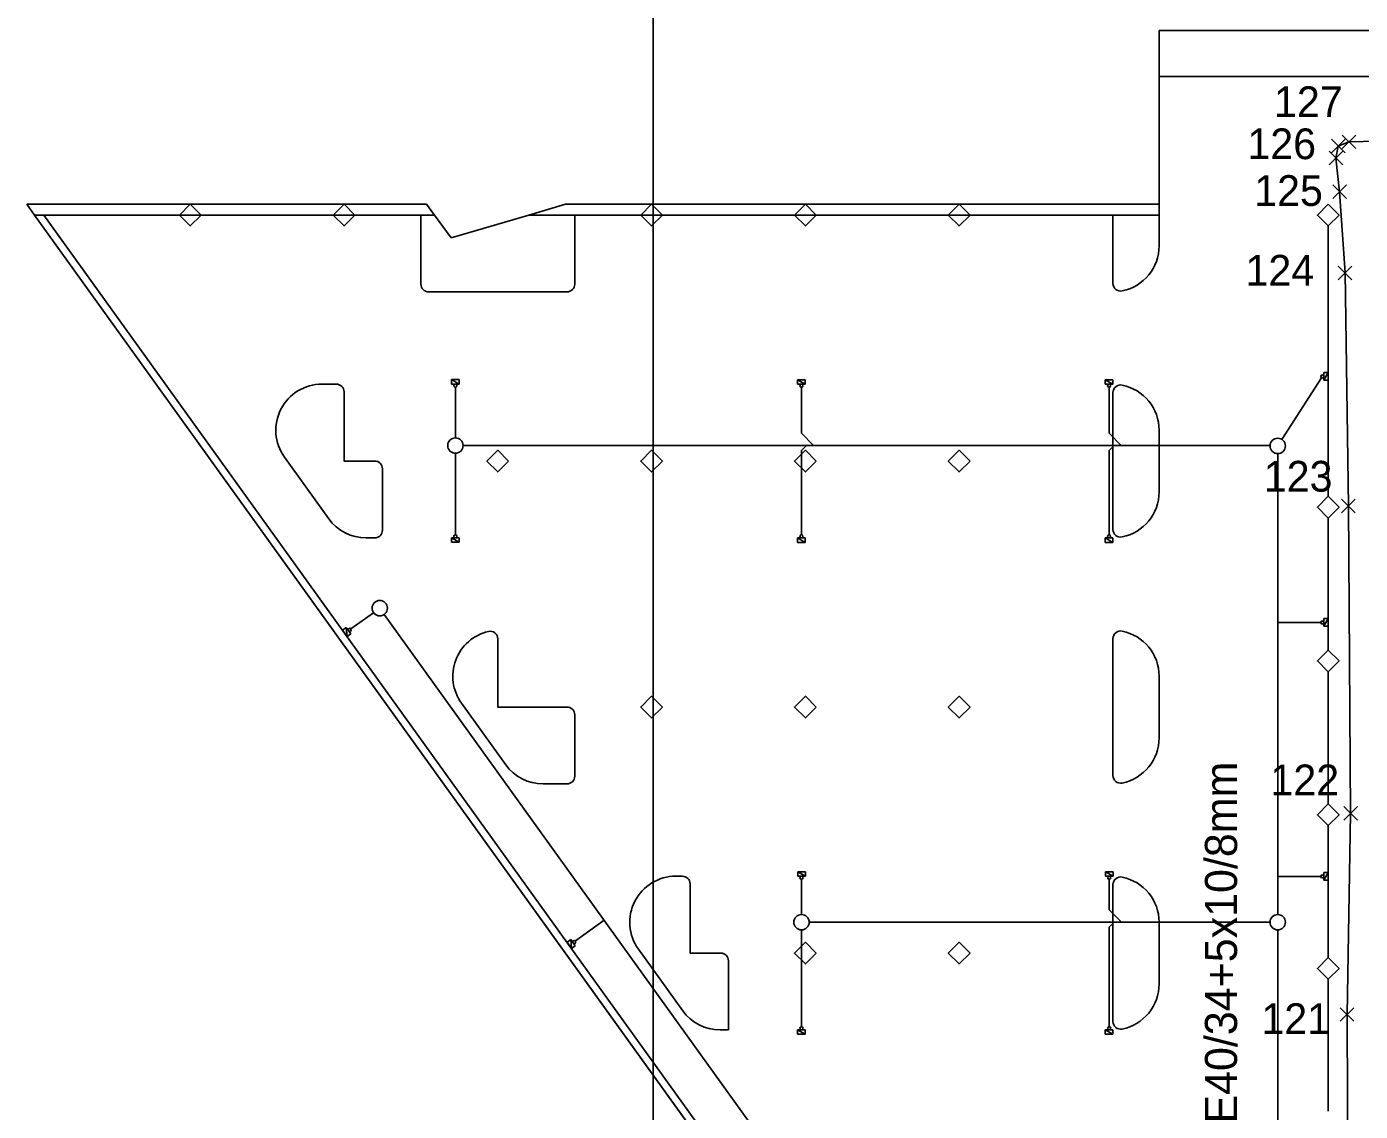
# Model space of a CAD drawing. Extents: x -264205 to -263744, y -1242450 to -1242050.
# Drawn here: x -264205.2 to -264118.5, y -1242249.8 to -1242179.2 of the extents above; entities that cross this region are included whole.
import ezdxf

# ---------------------------------------------------------------- set-up
doc = ezdxf.new("R2010")
doc.units = 0
for name, color, linetype in [('KFA_63-1_TELEKOM_PRELOZKA', 7, 'Continuous'), ('KFA_BODY_CISLO', 7, 'Continuous'), ('KFA_BODY_SYMBOL', 7, 'Continuous'), ('KFA_SITUACIA_DSP', 7, 'Continuous'), ('POPIS', 7, 'Continuous'), ('RAM_NA_TLAC_A3_1-1000', 7, 'Continuous')]:
    doc.layers.add(name, color=color, linetype=linetype)

msp = doc.modelspace()

# ---------------------------------------------------------------- linework, layer by layer
at = {"layer": 'KFA_63-1_TELEKOM_PRELOZKA'}
msp.add_lwpolyline([(-264117.865, -1242295.81), (-264119.153, -1242294.416), (-264119.323, -1242292.348), (-264119.1, -1242276.55), (-264119.268, -1242260.421), (-264119.343, -1242243.475), (-264119.114, -1242230.399), (-264119.258, -1242210.402), (-264119.476, -1242195.245), (-264119.832, -1242189.966), (-264120.07, -1242187.778), (-264119.914, -1242186.996), (-264119.225, -1242186.724), (-264097.679, -1242186.215)], dxfattribs=at)
at = {"layer": 'KFA_BODY_SYMBOL'}
for p, q in [((-264119.667, -1242187.166), (-264118.783, -1242186.282)), ((-264118.783, -1242187.166), (-264119.667, -1242186.282)), ((-264120.356, -1242187.438), (-264119.472, -1242186.554)), ((-264119.472, -1242187.438), (-264120.356, -1242186.554)), ((-264119.914, -1242186.996), (-264119.914, -1242186.996)), ((-264119.225, -1242186.724), (-264119.225, -1242186.724)), ((-264120.512, -1242188.22), (-264119.628, -1242187.336)), ((-264119.628, -1242188.22), (-264120.512, -1242187.336)), ((-264120.07, -1242187.778), (-264120.07, -1242187.778)), ((-264120.274, -1242190.408), (-264119.39, -1242189.524)), ((-264119.39, -1242190.408), (-264120.274, -1242189.524)), ((-264119.832, -1242189.966), (-264119.832, -1242189.966)), ((-264119.918, -1242195.687), (-264119.034, -1242194.803)), ((-264119.034, -1242195.687), (-264119.918, -1242194.803)), ((-264119.476, -1242195.245), (-264119.476, -1242195.245)), ((-264119.7, -1242210.844), (-264118.816, -1242209.96)), ((-264118.816, -1242210.844), (-264119.7, -1242209.96)), ((-264119.258, -1242210.402), (-264119.258, -1242210.402)), ((-264119.556, -1242230.841), (-264118.672, -1242229.957)), ((-264118.672, -1242230.841), (-264119.556, -1242229.957)), ((-264119.114, -1242230.399), (-264119.114, -1242230.399)), ((-264119.785, -1242243.917), (-264118.901, -1242243.033)), ((-264118.901, -1242243.917), (-264119.785, -1242243.033)), ((-264119.343, -1242243.475), (-264119.343, -1242243.475))]:
    msp.add_line(p, q, dxfattribs=at)
at = {"layer": 'KFA_SITUACIA_DSP'}
for p, q in [((-264131.568, -1242193.482), (-264131.568, -1242179.482)), ((-264077.23, -1242179.482), (-264131.568, -1242179.482)), ((-264131.568, -1242179.482), (-264131.568, -1242191.482)), ((-264131.568, -1242179.482), (-263959.468, -1242179.482)), ((-263959.468, -1242179.482), (-264131.568, -1242179.482)), ((-264045.204, -1242182.482), (-264131.568, -1242182.482)), ((-264205.202, -1242190.775), (-264179.193, -1242190.775)), ((-264205.202, -1242190.775), (-264204.694, -1242191.482)), ((-264178.679, -1242191.482), (-264204.694, -1242191.482)), ((-264204.694, -1242191.482), (-264115.871, -1242314.982)), ((-264179.568, -1242191.482), (-264204.078, -1242191.482)), ((-264204.078, -1242191.482), (-264119.75, -1242308.732)), ((-264179.568, -1242191.482), (-264179.568, -1242195.982)), ((-264179.193, -1242190.775), (-264178.679, -1242191.482)), ((-264177.6, -1242192.97), (-264178.679, -1242191.482)), ((-264172.558, -1242191.482), (-264177.6, -1242192.97)), ((-264172.558, -1242191.482), (-264170.162, -1242190.775)), ((-264131.568, -1242191.482), (-264172.558, -1242191.482)), ((-264170.162, -1242190.775), (-264131.568, -1242190.775)), ((-264134.568, -1242191.482), (-264169.568, -1242191.482)), ((-264169.568, -1242195.982), (-264169.568, -1242191.482)), ((-264134.568, -1242195.932), (-264134.568, -1242191.482)), ((-264120.568, -1242192.189), (-264120.568, -1242209.775)), ((-264179.068, -1242196.482), (-264170.068, -1242196.482)), ((-264120.858, -1242202.232), (-264120.858, -1242201.732)), ((-264120.858, -1242201.732), (-264120.568, -1242201.732)), ((-264120.858, -1242202.232), (-264120.568, -1242201.732)), ((-264120.858, -1242202.232), (-264120.568, -1242201.732)), ((-264120.568, -1242201.732), (-264120.858, -1242201.732)), ((-264120.858, -1242201.732), (-264120.858, -1242202.232)), ((-264120.568, -1242201.732), (-264120.568, -1242202.232)), ((-264185.068, -1242202.482), (-264186.002, -1242202.482)), ((-264177.574, -1242202.186), (-264177.074, -1242202.186)), ((-264177.574, -1242202.476), (-264177.574, -1242202.186)), ((-264177.574, -1242202.186), (-264177.074, -1242202.476)), ((-264177.574, -1242202.186), (-264177.074, -1242202.476)), ((-264177.074, -1242202.186), (-264177.574, -1242202.186)), ((-264177.074, -1242202.476), (-264177.574, -1242202.476)), ((-264177.324, -1242202.676), (-264177.324, -1242205.976)), ((-264177.074, -1242202.186), (-264177.074, -1242202.476)), ((-264177.074, -1242202.476), (-264177.074, -1242202.186)), ((-264155.074, -1242202.192), (-264154.574, -1242202.192)), ((-264155.074, -1242202.482), (-264155.074, -1242202.192)), ((-264155.074, -1242202.192), (-264154.574, -1242202.482)), ((-264155.074, -1242202.192), (-264154.574, -1242202.482)), ((-264154.574, -1242202.192), (-264155.074, -1242202.192)), ((-264154.574, -1242202.482), (-264155.074, -1242202.482)), ((-264154.824, -1242202.682), (-264154.824, -1242205.68)), ((-264154.574, -1242202.192), (-264154.574, -1242202.482)), ((-264154.574, -1242202.482), (-264154.574, -1242202.192)), ((-264135.068, -1242202.192), (-264134.568, -1242202.192)), ((-264135.068, -1242202.482), (-264135.068, -1242202.192)), ((-264135.068, -1242202.192), (-264134.568, -1242202.482)), ((-264135.068, -1242202.192), (-264134.568, -1242202.482)), ((-264134.568, -1242202.192), (-264135.068, -1242202.192)), ((-264134.568, -1242202.482), (-264135.068, -1242202.482)), ((-264134.818, -1242202.682), (-264134.818, -1242205.68)), ((-264134.568, -1242202.192), (-264134.568, -1242202.482)), ((-264134.568, -1242202.482), (-264134.568, -1242202.192)), ((-264121.012, -1242202.066), (-264123.585, -1242206.079)), ((-264120.568, -1242202.232), (-264120.858, -1242202.232)), ((-264134.568, -1242203.033), (-264134.568, -1242211.932)), ((-264154.824, -1242205.68), (-264154.029, -1242206.476)), ((-264134.818, -1242205.68), (-264134.023, -1242206.476)), ((-264131.568, -1242209.482), (-264131.568, -1242205.482)), ((-264177.324, -1242212.276), (-264177.324, -1242206.976)), ((-264176.824, -1242206.476), (-264124.354, -1242206.476)), ((-264154.824, -1242206.801), (-264154.499, -1242206.476)), ((-264154.824, -1242212.282), (-264154.824, -1242206.801)), ((-264134.818, -1242206.801), (-264134.493, -1242206.476)), ((-264134.818, -1242212.282), (-264134.818, -1242206.801)), ((-264123.854, -1242207), (-264123.854, -1242236.976)), ((-264188.438, -1242207.234), (-264185.561, -1242211.234)), ((-264182.068, -1242211.982), (-264182.068, -1242207.982)), ((-264120.568, -1242211.189), (-264120.568, -1242219.774)), ((-264183.125, -1242212.482), (-264182.568, -1242212.482)), ((-264177.574, -1242212.476), (-264177.074, -1242212.476)), ((-264177.574, -1242212.766), (-264177.574, -1242212.476)), ((-264177.574, -1242212.476), (-264177.074, -1242212.766)), ((-264177.574, -1242212.476), (-264177.074, -1242212.766)), ((-264177.074, -1242212.476), (-264177.574, -1242212.476)), ((-264177.074, -1242212.766), (-264177.574, -1242212.766)), ((-264177.074, -1242212.476), (-264177.074, -1242212.766)), ((-264177.074, -1242212.766), (-264177.074, -1242212.476)), ((-264155.074, -1242212.482), (-264154.574, -1242212.482)), ((-264155.074, -1242212.772), (-264155.074, -1242212.482)), ((-264155.074, -1242212.482), (-264154.574, -1242212.772)), ((-264155.074, -1242212.482), (-264154.574, -1242212.772)), ((-264154.574, -1242212.482), (-264155.074, -1242212.482)), ((-264154.574, -1242212.772), (-264155.074, -1242212.772)), ((-264154.574, -1242212.482), (-264154.574, -1242212.772)), ((-264154.574, -1242212.772), (-264154.574, -1242212.482)), ((-264135.068, -1242212.482), (-264134.568, -1242212.482)), ((-264135.068, -1242212.772), (-264135.068, -1242212.482)), ((-264135.068, -1242212.482), (-264134.568, -1242212.772)), ((-264135.068, -1242212.482), (-264134.568, -1242212.772)), ((-264134.568, -1242212.482), (-264135.068, -1242212.482)), ((-264134.568, -1242212.772), (-264135.068, -1242212.772)), ((-264134.568, -1242212.482), (-264134.568, -1242212.772)), ((-264134.568, -1242212.772), (-264134.568, -1242212.482)), ((-264184.115, -1242218.399), (-264182.649, -1242217.344)), ((-264181.951, -1242217.458), (-264153.34, -1242257.238)), ((-264184.659, -1242218.482), (-264184.424, -1242218.313)), ((-264184.367, -1242218.888), (-264184.659, -1242218.482)), ((-264184.424, -1242218.313), (-264184.132, -1242218.719)), ((-264184.424, -1242218.313), (-264184.367, -1242218.888)), ((-264184.424, -1242218.313), (-264184.367, -1242218.888)), ((-264184.132, -1242218.719), (-264184.424, -1242218.313)), ((-264121.058, -1242217.982), (-264123.854, -1242217.982)), ((-264120.86, -1242218.232), (-264120.86, -1242217.732)), ((-264120.86, -1242217.732), (-264120.57, -1242217.732)), ((-264120.86, -1242218.232), (-264120.57, -1242217.732)), ((-264120.86, -1242218.232), (-264120.57, -1242217.732)), ((-264120.57, -1242217.732), (-264120.86, -1242217.732)), ((-264120.86, -1242217.732), (-264120.86, -1242218.232)), ((-264120.57, -1242218.232), (-264120.86, -1242218.232)), ((-264120.57, -1242217.732), (-264120.57, -1242218.232)), ((-264184.132, -1242218.719), (-264184.367, -1242218.888)), ((-264184.367, -1242218.888), (-264184.132, -1242218.719)), ((-264134.568, -1242219.033), (-264134.568, -1242227.932)), ((-264131.568, -1242225.482), (-264131.568, -1242221.482)), ((-264120.568, -1242221.189), (-264120.568, -1242229.774)), ((-264176.93, -1242223.234), (-264174.054, -1242227.234)), ((-264169.568, -1242227.982), (-264169.568, -1242223.982)), ((-264171.618, -1242228.482), (-264170.068, -1242228.482)), ((-264120.568, -1242231.189), (-264120.568, -1242239.774)), ((-264162.988, -1242234.482), (-264162.568, -1242234.482)), ((-264155.068, -1242234.192), (-264154.568, -1242234.192)), ((-264155.068, -1242234.482), (-264155.068, -1242234.192)), ((-264155.068, -1242234.192), (-264154.568, -1242234.482)), ((-264155.068, -1242234.192), (-264154.568, -1242234.482)), ((-264154.568, -1242234.192), (-264155.068, -1242234.192)), ((-264154.568, -1242234.482), (-264155.068, -1242234.482)), ((-264154.818, -1242234.682), (-264154.818, -1242236.976)), ((-264154.568, -1242234.192), (-264154.568, -1242234.482)), ((-264154.568, -1242234.482), (-264154.568, -1242234.192)), ((-264135.061, -1242234.192), (-264134.561, -1242234.192)), ((-264135.061, -1242234.482), (-264135.061, -1242234.192)), ((-264135.061, -1242234.192), (-264134.561, -1242234.482)), ((-264135.061, -1242234.192), (-264134.561, -1242234.482)), ((-264134.561, -1242234.192), (-264135.061, -1242234.192)), ((-264134.561, -1242234.482), (-264135.061, -1242234.482)), ((-264134.811, -1242234.682), (-264134.811, -1242236.68)), ((-264134.561, -1242234.192), (-264134.561, -1242234.482)), ((-264134.561, -1242234.482), (-264134.561, -1242234.192)), ((-264121.058, -1242234.499), (-264123.854, -1242234.499)), ((-264120.858, -1242234.749), (-264120.858, -1242234.249)), ((-264120.858, -1242234.249), (-264120.568, -1242234.249)), ((-264120.858, -1242234.749), (-264120.568, -1242234.249)), ((-264120.858, -1242234.749), (-264120.568, -1242234.249)), ((-264120.568, -1242234.249), (-264120.858, -1242234.249)), ((-264120.858, -1242234.249), (-264120.858, -1242234.749)), ((-264120.568, -1242234.749), (-264120.858, -1242234.749)), ((-264120.568, -1242234.249), (-264120.568, -1242234.749)), ((-264162.068, -1242239.482), (-264162.068, -1242234.982)), ((-264134.568, -1242235.033), (-264134.568, -1242243.932)), ((-264134.811, -1242236.68), (-264134.016, -1242237.476)), ((-264169.518, -1242238.695), (-264167.646, -1242237.348)), ((-264154.318, -1242237.476), (-264124.354, -1242237.476)), ((-264134.811, -1242237.801), (-264134.486, -1242237.476)), ((-264131.568, -1242241.482), (-264131.568, -1242237.482)), ((-264154.824, -1242244.276), (-264154.824, -1242237.976)), ((-264134.811, -1242244.276), (-264134.811, -1242237.801)), ((-264123.854, -1242237.976), (-264123.854, -1242297.736)), ((-264170.062, -1242238.778), (-264169.827, -1242238.609)), ((-264169.77, -1242239.184), (-264170.062, -1242238.778)), ((-264169.827, -1242238.609), (-264169.535, -1242239.015)), ((-264169.827, -1242238.609), (-264169.77, -1242239.184)), ((-264169.827, -1242238.609), (-264169.77, -1242239.184)), ((-264169.535, -1242239.015), (-264169.827, -1242238.609)), ((-264169.535, -1242239.015), (-264169.77, -1242239.184)), ((-264169.77, -1242239.184), (-264169.535, -1242239.015)), ((-264165.423, -1242239.234), (-264162.546, -1242243.234)), ((-264162.068, -1242239.482), (-264160.068, -1242239.482)), ((-264159.568, -1242239.982), (-264159.568, -1242244.482)), ((-264120.568, -1242241.189), (-264120.568, -1242249.774)), ((-264160.111, -1242244.482), (-264159.568, -1242244.482)), ((-264155.074, -1242244.476), (-264154.574, -1242244.476)), ((-264155.074, -1242244.766), (-264155.074, -1242244.476)), ((-264155.074, -1242244.476), (-264154.574, -1242244.766)), ((-264155.074, -1242244.476), (-264154.574, -1242244.766)), ((-264154.574, -1242244.476), (-264155.074, -1242244.476)), ((-264154.574, -1242244.476), (-264154.574, -1242244.766)), ((-264154.574, -1242244.766), (-264154.574, -1242244.476)), ((-264135.068, -1242244.476), (-264134.568, -1242244.476)), ((-264135.068, -1242244.766), (-264135.068, -1242244.476)), ((-264135.068, -1242244.476), (-264134.568, -1242244.766)), ((-264135.068, -1242244.476), (-264134.568, -1242244.766)), ((-264134.568, -1242244.476), (-264135.068, -1242244.476)), ((-264134.568, -1242244.476), (-264134.568, -1242244.766)), ((-264134.568, -1242244.766), (-264134.568, -1242244.476)), ((-264154.574, -1242244.766), (-264155.074, -1242244.766)), ((-264134.568, -1242244.766), (-264135.068, -1242244.766))]:
    msp.add_line(p, q, dxfattribs=at)
for points in [[(-264204.694, -1242191.482), (-264137.78, -1242284.52), (-264125.581, -1242301.482)], [(-264193.861, -1242191.482), (-264193.861, -1242191.482), (-264194.568, -1242192.189), (-264195.275, -1242191.482)], [(-264183.861, -1242191.482), (-264183.861, -1242191.482), (-264184.568, -1242192.189), (-264185.275, -1242191.482)], [(-264163.861, -1242191.482), (-264163.861, -1242191.482), (-264164.568, -1242192.189), (-264165.275, -1242191.482)], [(-264153.861, -1242191.482), (-264153.861, -1242191.482), (-264154.568, -1242192.189), (-264155.275, -1242191.482)], [(-264143.861, -1242191.482), (-264143.861, -1242191.482), (-264144.568, -1242192.189), (-264145.275, -1242191.482)], [(-264182.568, -1242207.482), (-264184.568, -1242207.482), (-264184.568, -1242202.982)], [(-264170.068, -1242223.482), (-264174.568, -1242223.482), (-264174.568, -1242219.049)]]:
    msp.add_lwpolyline(points, dxfattribs=at)
for points in [[(-264194.568, -1242190.775), (-264193.861, -1242191.482), (-264194.568, -1242192.189), (-264195.275, -1242191.482)], [(-264184.568, -1242190.775), (-264183.861, -1242191.482), (-264184.568, -1242192.189), (-264185.275, -1242191.482)], [(-264164.568, -1242190.775), (-264163.861, -1242191.482), (-264164.568, -1242192.189), (-264165.275, -1242191.482)], [(-264154.568, -1242190.775), (-264153.861, -1242191.482), (-264154.568, -1242192.189), (-264155.275, -1242191.482)], [(-264144.568, -1242190.775), (-264143.861, -1242191.482), (-264144.568, -1242192.189), (-264145.275, -1242191.482)], [(-264120.568, -1242190.775), (-264119.861, -1242191.482), (-264120.568, -1242192.189), (-264121.275, -1242191.482)], [(-264173.861, -1242207.482), (-264174.568, -1242206.775), (-264175.275, -1242207.482), (-264174.568, -1242208.189)], [(-264163.861, -1242207.482), (-264164.568, -1242206.775), (-264165.275, -1242207.482), (-264164.568, -1242208.189)], [(-264153.861, -1242207.482), (-264154.568, -1242206.775), (-264155.275, -1242207.482), (-264154.568, -1242208.189)], [(-264143.861, -1242207.482), (-264144.568, -1242206.775), (-264145.275, -1242207.482), (-264144.568, -1242208.189)], [(-264120.568, -1242209.775), (-264119.861, -1242210.482), (-264120.568, -1242211.189), (-264121.275, -1242210.482)], [(-264120.568, -1242219.775), (-264119.861, -1242220.482), (-264120.568, -1242221.189), (-264121.275, -1242220.482)], [(-264163.861, -1242223.482), (-264164.568, -1242222.775), (-264165.275, -1242223.482), (-264164.568, -1242224.189)], [(-264153.861, -1242223.482), (-264154.568, -1242222.775), (-264155.275, -1242223.482), (-264154.568, -1242224.189)], [(-264143.861, -1242223.482), (-264144.568, -1242222.775), (-264145.275, -1242223.482), (-264144.568, -1242224.189)], [(-264120.568, -1242229.775), (-264119.861, -1242230.482), (-264120.568, -1242231.189), (-264121.275, -1242230.482)], [(-264153.861, -1242239.482), (-264154.568, -1242238.775), (-264155.275, -1242239.482), (-264154.568, -1242240.189)], [(-264143.861, -1242239.482), (-264144.568, -1242238.775), (-264145.275, -1242239.482), (-264144.568, -1242240.189)], [(-264120.568, -1242239.775), (-264119.861, -1242240.482), (-264120.568, -1242241.189), (-264121.275, -1242240.482)]]:
    msp.add_lwpolyline(points, close=True, dxfattribs=at)
for centre, radius in [((-264120.958, -1242201.982), 0.1), ((-264177.324, -1242202.576), 0.1), ((-264154.824, -1242202.582), 0.1), ((-264134.818, -1242202.582), 0.1), ((-264177.324, -1242206.476), 0.5), ((-264123.854, -1242206.5), 0.5), ((-264177.324, -1242212.376), 0.1), ((-264154.824, -1242212.382), 0.1), ((-264134.818, -1242212.382), 0.1), ((-264182.243, -1242217.052), 0.5), ((-264184.194, -1242218.461), 0.1), ((-264120.958, -1242217.982), 0.1), ((-264154.818, -1242234.582), 0.1), ((-264134.811, -1242234.582), 0.1), ((-264120.958, -1242234.499), 0.1), ((-264154.818, -1242237.476), 0.5), ((-264123.854, -1242237.476), 0.5), ((-264169.597, -1242238.757), 0.1), ((-264154.818, -1242244.376), 0.1), ((-264134.811, -1242244.376), 0.1)]:
    msp.add_circle(centre, radius, dxfattribs=at)
for centre, radius, start, end in [((-264134.568, -1242193.482), 3, 281.53696, 0), ((-264134.068, -1242195.932), 0.5, 180, 281.53696), ((-264179.068, -1242195.982), 0.5, 180, 270), ((-264170.068, -1242195.982), 0.5, 270, 0), ((-264186.002, -1242205.482), 3, 90, 215.72401), ((-264185.068, -1242202.982), 0.5, 0, 90), ((-264134.068, -1242203.033), 0.5, 78.46304, 180), ((-264134.568, -1242205.482), 3, 0, 78.46304), ((-264182.568, -1242207.982), 0.5, 0, 90), ((-264134.568, -1242209.482), 3, 281.53696, 0), ((-264183.125, -1242209.482), 3, 215.72401, 270), ((-264182.568, -1242211.982), 0.5, 270, 0), ((-264134.068, -1242211.932), 0.5, 180, 281.53696), ((-264174.495, -1242221.482), 3, 103.24756, 215.72401), ((-264175.068, -1242219.049), 0.5, 0, 103.24756), ((-264134.068, -1242219.033), 0.5, 78.46304, 180), ((-264134.568, -1242221.482), 3, 0, 78.46304), ((-264170.068, -1242223.982), 0.5, 0, 90), ((-264134.568, -1242225.482), 3, 281.53696, 0), ((-264171.618, -1242225.482), 3, 215.72401, 270), ((-264170.068, -1242227.982), 0.5, 270, 0), ((-264134.068, -1242227.932), 0.5, 180, 281.53696), ((-264162.988, -1242237.482), 3, 90, 215.72401), ((-264162.568, -1242234.982), 0.5, 0, 90), ((-264134.068, -1242235.033), 0.5, 78.46304, 180), ((-264134.568, -1242237.482), 3, 0, 78.46304), ((-264160.068, -1242239.982), 0.5, 0, 90), ((-264134.568, -1242241.482), 3, 281.53696, 0), ((-264160.111, -1242241.482), 3, 215.72401, 270), ((-264134.068, -1242243.932), 0.5, 180, 281.53696)]:
    msp.add_arc(centre, radius, start, end, dxfattribs=at)
at = {"layer": 'RAM_NA_TLAC_A3_1-1000'}
msp.add_lwpolyline([(-264164.47, -1242072.566), (-263744.47, -1242072.566), (-263744.47, -1242369.566), (-264164.47, -1242369.566)], close=True, dxfattribs=at)

# ---------------------------------------------------------------- texts
at = {"layer": 'KFA_BODY_CISLO'}
for s, p in [('127', (-264124.094, -1242185.115)), ('126', (-264125.825, -1242187.849)), ('125', (-264125.381, -1242190.892)), ('124', (-264125.947, -1242196.076)), ('123', (-264124.756, -1242209.472)), ('122', (-264124.323, -1242229.221)), ('121', (-264124.914, -1242244.749))]:
    msp.add_text(s, height=2, dxfattribs=at).set_placement(p)
at = {"layer": 'POPIS'}
msp.add_text('HDPE40/34+5x10/8mm', height=2.09, rotation=90, dxfattribs=at).set_placement((-264126.497, -1242256.471))

doc.saveas('drawing.dxf')
